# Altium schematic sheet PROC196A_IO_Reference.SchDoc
size A2; Date: Not shown in title block; ApprovedBy: Not shown in title block; CheckedBy: Not shown in title block; Author: Not shown in title block; CompanyName: Not shown in title block; Engineer: Not shown in title block; Organization: Not shown in title block; Address1: Not shown in title block; Address2: Not shown in title block; Address3: Not shown in title block; Address4: Not shown in title block; DocumentNumber: 2; Revision: Use project parameter SCH_Rev; SheetNumber: 2; SheetTotal: 25; PageSetup: Record=PageOptions¦CenterHorizontal=True¦CenterVertical=True¦PrintScale=1.00¦XCorrection=1.00¦YCorrection=1.00¦PrintKind=0¦BorderSize=5000000¦LeftOffset=0¦BottomOffset=0¦Orientation=2¦PaperLength=1000¦PaperWidth=1000¦Scale=100¦PaperSource=15¦PrintQuality=600¦MediaType=1¦DitherType=10¦PaperKind=Letter¦PrintScaleMode=1
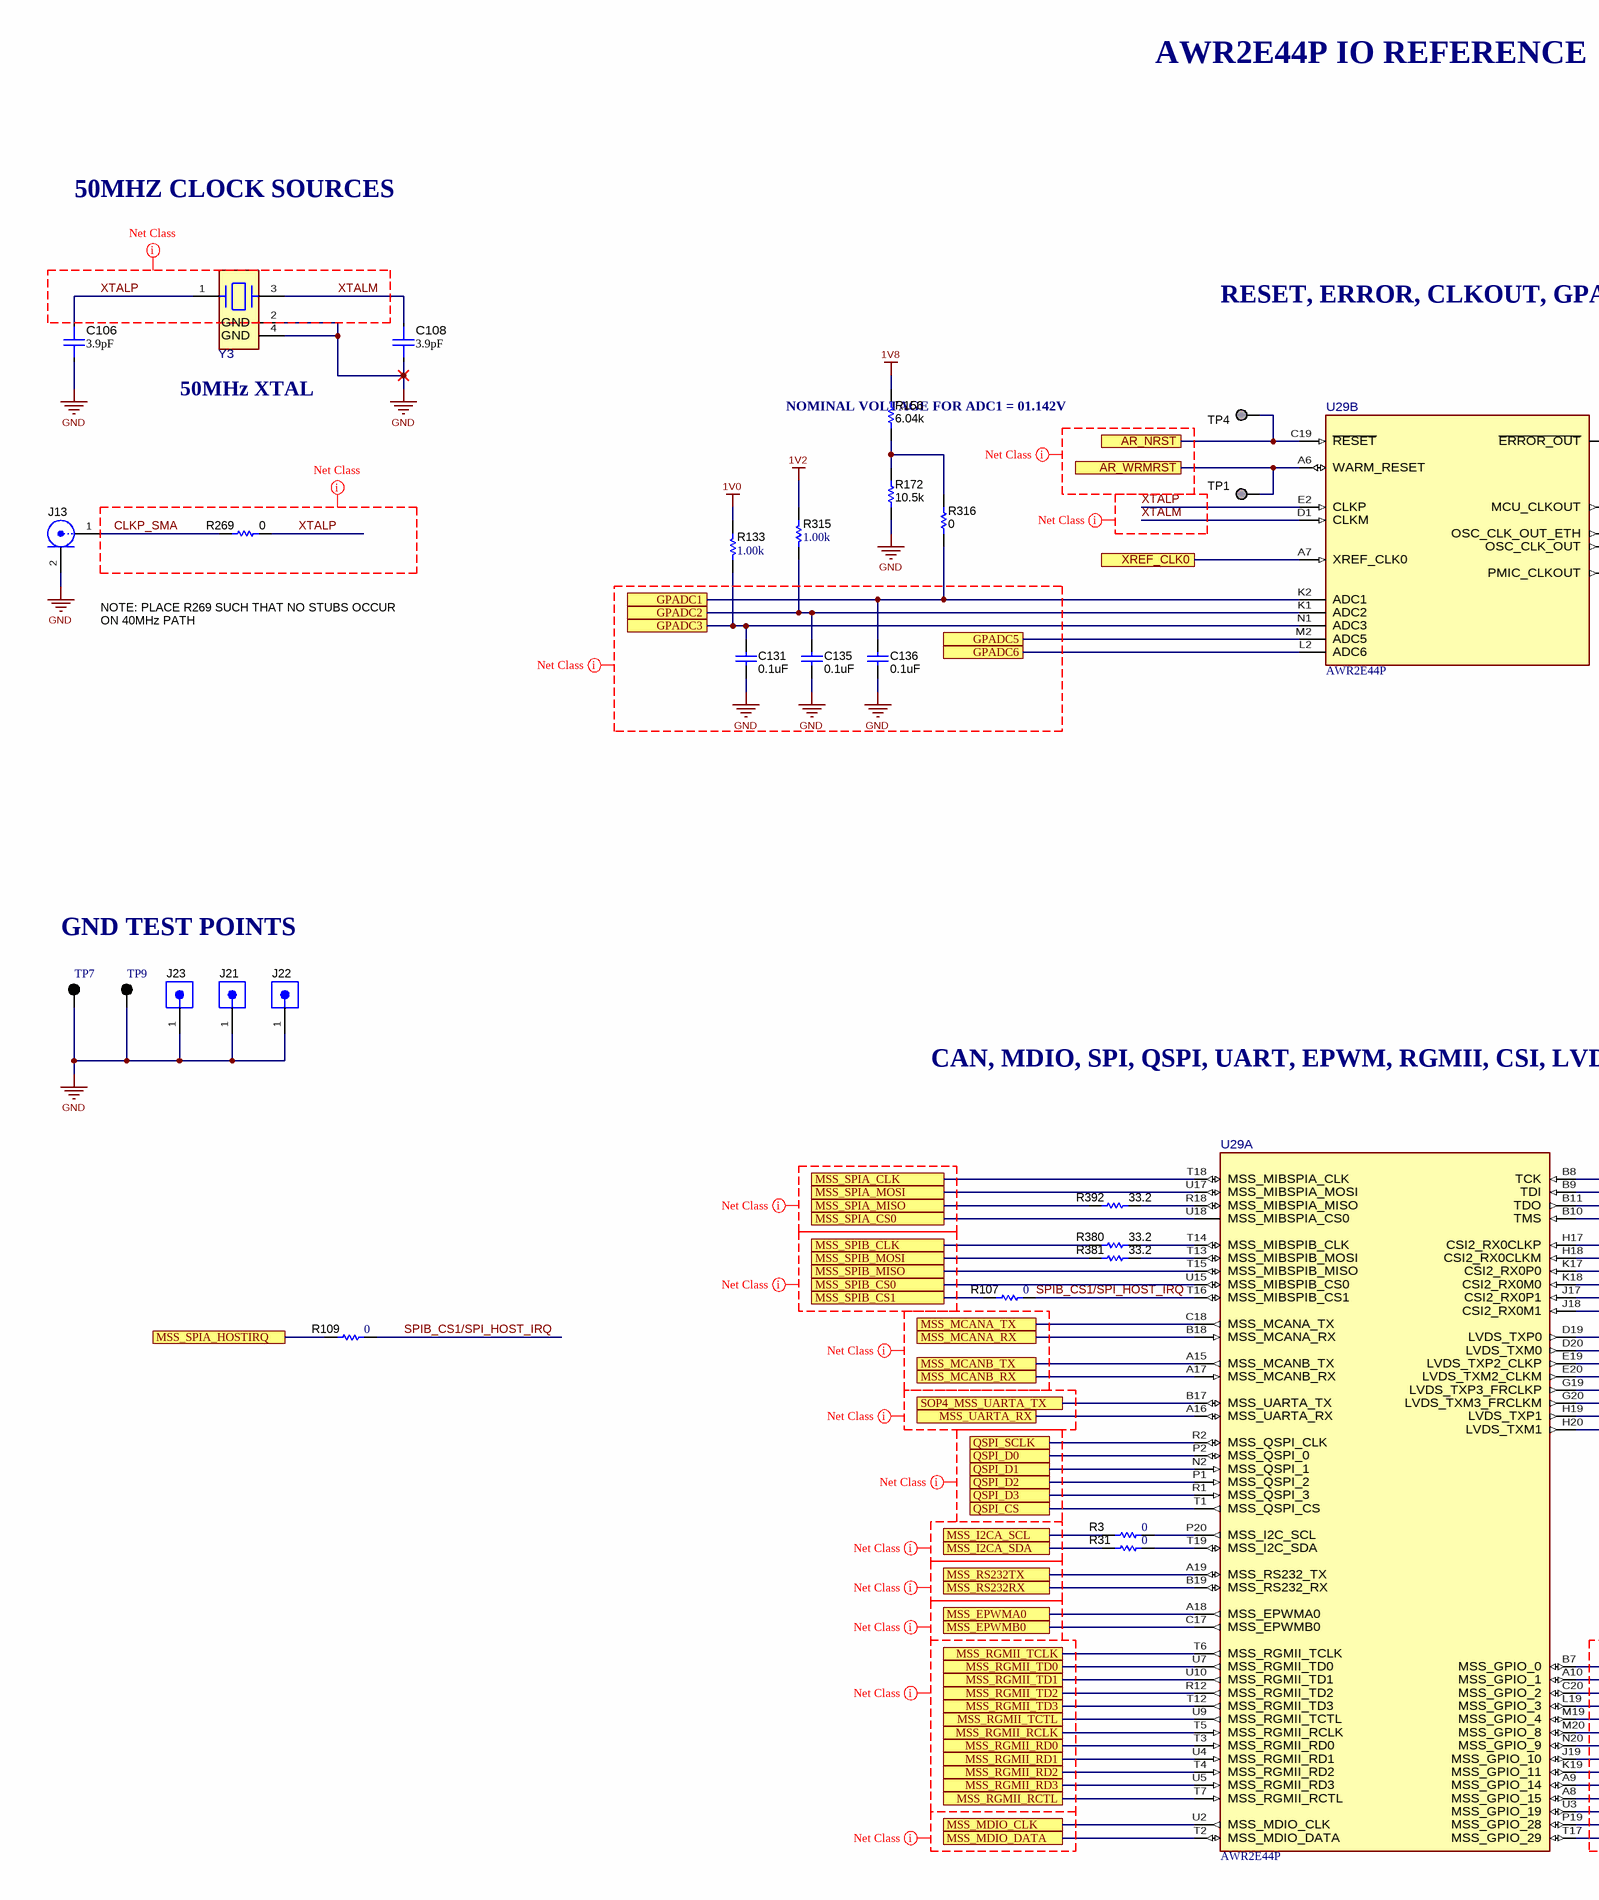
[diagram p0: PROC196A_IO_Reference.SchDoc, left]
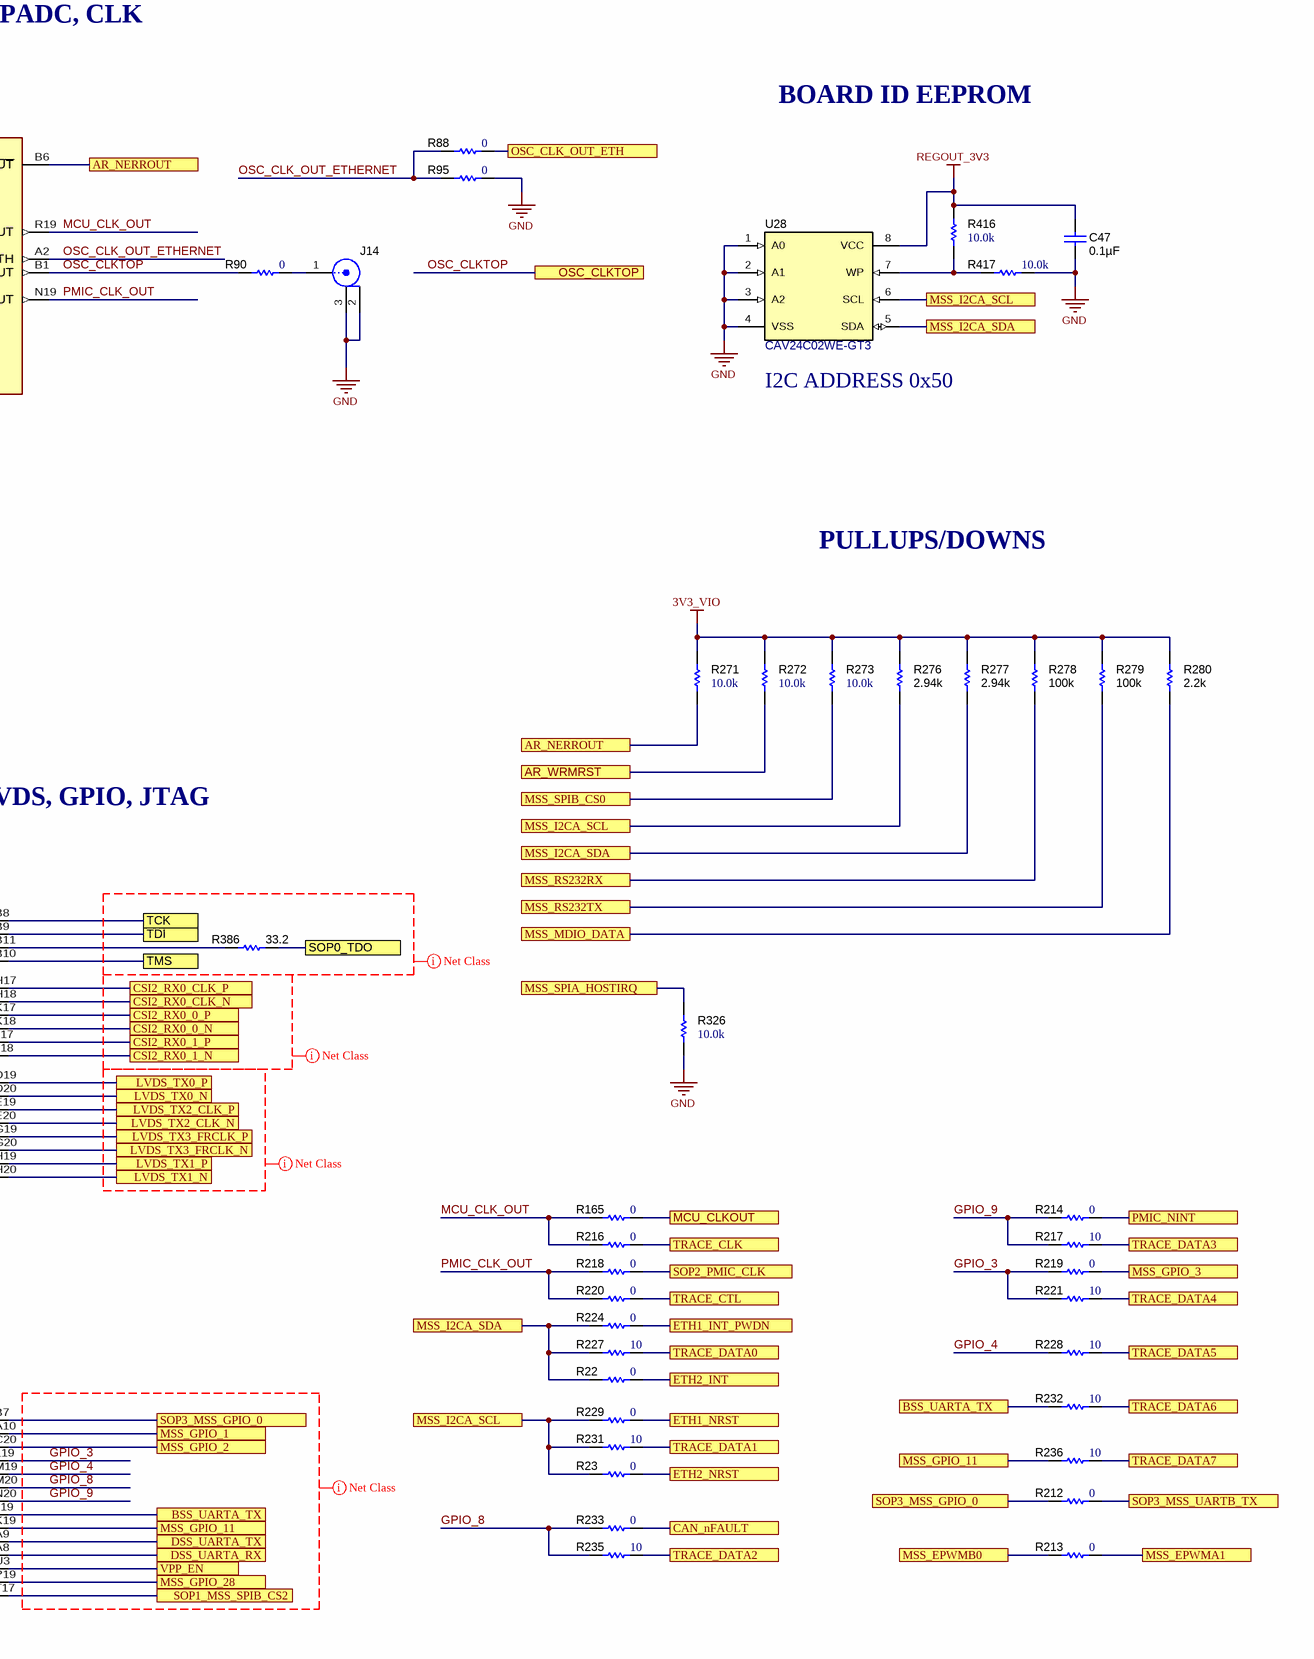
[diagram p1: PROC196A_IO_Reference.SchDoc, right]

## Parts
C47  ValueDisplayed: 0.1µF  [0402L]  (hidden comment: C0402C104K8RACTU)
C106  ValueDisplayed: 3.9pF  [FP-GCM1555C1H3R9BA16D_0402-MFG]  (hidden comment: GCM1555C1H3R9BA16D)
C108  ValueDisplayed: 3.9pF  [FP-GCM1555C1H3R9BA16D_0402-MFG]  (hidden comment: GCM1555C1H3R9BA16D)
C131  ValueDisplayed: 0.1uF  [0402L]  (hidden comment: GCM155R71C104KA55D)
C135  ValueDisplayed: 0.1uF  [0402L]  (hidden comment: GCM155R71C104KA55D)
C136  ValueDisplayed: 0.1uF  [0402L]  (hidden comment: GCM155R71C104KA55D)
J13  142-0711-201  [142-0711-201]  (value not drawn)
J14  128-0711-201  [Johnson_128-0711-201]  (value not drawn)
J21  GBC01SFBN-M30  [Sullins_GBC01SFBN-M30]  (value not drawn)
J22  GBC01SFBN-M30  [Sullins_GBC01SFBN-M30]  (value not drawn)
J23  GBC01SFBN-M30  [Sullins_GBC01SFBN-M30]  (value not drawn)
R3  ValueDisplayed: 0  [0402L]  (hidden comment: ERJ-2GE0R00X)
R22  ValueDisplayed: 0  [0402L]  (hidden comment: ERJ-2GE0R00X)
R23  ValueDisplayed: 0  [0402L]  (hidden comment: ERJ-2GE0R00X)
R31  ValueDisplayed: 0  [0402L]  (hidden comment: ERJ-2GE0R00X)
R88  ValueDisplayed: 0  [0402L]  (hidden comment: ERJ-2GE0R00X)
R90  ValueDisplayed: 0  [0402L]  (hidden comment: ERJ-2GE0R00X)
R95  ValueDisplayed: 0  [0402L]  (hidden comment: ERJ-2GE0R00X)
R107  ValueDisplayed: 0  [0402L]  (hidden comment: ERJ-2GE0R00X)
R109  ValueDisplayed: 0  [0402L]  (hidden comment: ERJ-2GE0R00X)
R133  ValueDisplayed: 1.00k  [0402L]  (hidden comment: CRCW04021K00FKED)
R156  ValueDisplayed: 6.04k  [0402L]  (hidden comment: CRCW04026K04FKED)
R165  ValueDisplayed: 0  [0201L]  (hidden comment: CRCW02010000Z0ED)
R172  ValueDisplayed: 10.5k  [0402L]  (hidden comment: CRCW040210K5FKED)
R212  ValueDisplayed: 0  [0201L]  (hidden comment: CRCW02010000Z0ED)
R213  value 0  [0402L]  (hidden comment: ERJ-2GE0R00X)
R214  value 0  [0402L]  (hidden comment: ERJ-2GE0R00X)
R216  ValueDisplayed: 0  [0201L]  (hidden comment: CRCW02010000Z0ED)
R217  ValueDisplayed: 10  [0201L]  (hidden comment: RC0201JR-0710RL)
R218  ValueDisplayed: 0  [0201L]  (hidden comment: CRCW02010000Z0ED)
R219  ValueDisplayed: 0  [0201L]  (hidden comment: CRCW02010000Z0ED)
R220  ValueDisplayed: 0  [0201L]  (hidden comment: CRCW02010000Z0ED)
R221  ValueDisplayed: 10  [0201L]  (hidden comment: RC0201JR-0710RL)
R224  ValueDisplayed: 0  [0201L]  (hidden comment: CRCW02010000Z0ED)
R227  ValueDisplayed: 10  [0201L]  (hidden comment: RC0201JR-0710RL)
R228  ValueDisplayed: 10  [0201L]  (hidden comment: RC0201JR-0710RL)
R229  ValueDisplayed: 0  [0201L]  (hidden comment: CRCW02010000Z0ED)
R231  ValueDisplayed: 10  [0201L]  (hidden comment: RC0201JR-0710RL)
R232  ValueDisplayed: 10  [0201L]  (hidden comment: RC0201JR-0710RL)
R233  value 0  [0402L]  (hidden comment: ERJ-2GE0R00X)
R235  ValueDisplayed: 10  [0201L]  (hidden comment: RC0201JR-0710RL)
R236  ValueDisplayed: 10  [0201L]  (hidden comment: RC0201JR-0710RL)
R269  ValueDisplayed: 0  [0402L]  (hidden comment: ERJ-2GE0R00X)
R271  ValueDisplayed: 10.0k  [0402L]  (hidden comment: CRCW040210K0FKED)
R272  ValueDisplayed: 10.0k  [0402L]  (hidden comment: CRCW040210K0FKED)
R273  ValueDisplayed: 10.0k  [0402L]  (hidden comment: CRCW040210K0FKED)
R276  ValueDisplayed: 2.94k  [0402L]  (hidden comment: CRCW04022K94FKED)
R277  ValueDisplayed: 2.94k  [0402L]  (hidden comment: CRCW04022K94FKED)
R278  ValueDisplayed: 100k  [0402L]  (hidden comment: CRCW0402100KFKED)
R279  ValueDisplayed: 100k  [0402L]  (hidden comment: CRCW0402100KFKED)
R280  ValueDisplayed: 2.2k  [0402L]  (hidden comment: CRCW04022K20JNED)
R315  ValueDisplayed: 1.00k  [0402L]  (hidden comment: CRCW04021K00FKED)
R316  ValueDisplayed: 0  [0402L]  (hidden comment: ERJ-2GE0R00X)
R326  ValueDisplayed: 10.0k  [0402L]  (hidden comment: CRCW040210K0FKED)
R380  ValueDisplayed: 33.2  [0402L]  (hidden comment: CRCW040233R2FKED)
R381  ValueDisplayed: 33.2  [0402L]  (hidden comment: CRCW040233R2FKED)
R386  ValueDisplayed: 33.2  [0402L]  (hidden comment: CRCW040233R2FKED)
R392  ValueDisplayed: 33.2  [0402L]  (hidden comment: CRCW040233R2FKED)
R416  ValueDisplayed: 10.0k  [0402L]  (hidden comment: CRCW040210K0FKED)
R417  ValueDisplayed: 10.0k  [0402L]  (hidden comment: CRCW040210K0FKED)
TP1  TESTPOINT  [TP_25MIL-SMT]  (value not drawn)  (no BOM)
TP4  TESTPOINT  [TP_25MIL-SMT]  (value not drawn)  (no BOM)
TP7  5001  [Keystone5001]  (value not drawn)
TP9  5001  [Keystone5001]  (value not drawn)
U28  CAV24C02WE-GT3  [SOIC-8]
U29  AWR2E44P  [AMX0278A-MFG]  (parts A,B of 6)
Y3  NX2016SA-50M-STD-CZS-3  [FP-NX2016SA-50M-STD-CZS-3_SMT4_2MM0_1MM6-MFG]  (value not drawn)

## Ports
AR_NERROUT, AR_NRST, AR_WRMRST, BSS_UARTA_TX, CAN_nFAULT, CSI2_RX0_0_N, CSI2_RX0_0_P, CSI2_RX0_1_N, CSI2_RX0_1_P, CSI2_RX0_CLK_N, CSI2_RX0_CLK_P, DSS_UARTA_RX, DSS_UARTA_TX, ETH1_INT_PWDN, ETH1_NRST, ETH2_INT, ETH2_NRST, GPADC1, GPADC2, GPADC3, GPADC5, GPADC6, LVDS_TX0_N, LVDS_TX0_P, LVDS_TX1_N, LVDS_TX1_P, LVDS_TX2_CLK_N, LVDS_TX2_CLK_P, LVDS_TX3_FRCLK_N, LVDS_TX3_FRCLK_P, MCU_CLKOUT, MSS_EPWMA0, MSS_EPWMA1, MSS_EPWMB0, MSS_GPIO_1, MSS_GPIO_2, MSS_GPIO_3, MSS_GPIO_11, MSS_GPIO_28, MSS_I2CA_SCL, MSS_I2CA_SDA, MSS_MCANA_RX, MSS_MCANA_TX, MSS_MCANB_RX, MSS_MCANB_TX, MSS_MDIO_CLK, MSS_MDIO_DATA, MSS_RGMII_RCLK, MSS_RGMII_RCTL, MSS_RGMII_RD0, MSS_RGMII_RD1, MSS_RGMII_RD2, MSS_RGMII_RD3, MSS_RGMII_TCLK, MSS_RGMII_TCTL, MSS_RGMII_TD0, MSS_RGMII_TD1, MSS_RGMII_TD2, MSS_RGMII_TD3, MSS_RS232RX, MSS_RS232TX, MSS_SPIA_CLK, MSS_SPIA_CS0, MSS_SPIA_HOSTIRQ, MSS_SPIA_MISO, MSS_SPIA_MOSI, MSS_SPIB_CLK, MSS_SPIB_CS0, MSS_SPIB_CS1, MSS_SPIB_MISO, MSS_SPIB_MOSI, MSS_UARTA_RX, OSC_CLK_OUT_ETH, OSC_CLKTOP, PMIC_NINT, QSPI_CS, QSPI_D0, QSPI_D1, QSPI_D2, QSPI_D3, QSPI_SCLK, SOP0_TDO, SOP1_MSS_SPIB_CS2, SOP2_PMIC_CLK, SOP3_MSS_GPIO_0, SOP3_MSS_UARTB_TX, SOP4_MSS_UARTA_TX, TCK, TDI, TMS, TRACE_CLK, TRACE_CTL, TRACE_DATA0, TRACE_DATA1, TRACE_DATA2, TRACE_DATA3, TRACE_DATA4, TRACE_DATA5, TRACE_DATA6, TRACE_DATA7, VPP_EN, XREF_CLK0

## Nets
1V0: R133.2
1V2: R315.2
1V8: R156.2
3V3_VIO: R271.2 R272.2 R273.2 R276.2 R277.2 R278.2 R279.2 R280.2
GND: C47.1 C106.2 C108.2 C131.1 C135.1 C136.1 J13.2 J14.2 J14.3 J21.1 J22.1 J23.1 R95.1 R172.1 R326.1 R417.1 TP7.1 TP9.1 U28.1(A0) U28.2(A1) U28.3(A2) U28.4(VSS) Y3.2(GND) Y3.4(GND)
REGOUT_3V3: C47.2 R416.2 U28.8(VCC)
AR_NERROUT: R271.1 U29.B6(~{ERROR_OUT}) ; port AR_NERROUT
AR_NRST: TP4.1 U29.C19(~{RESET}) ; port AR_NRST
AR_WRMRST: R272.1 TP1.1 U29.A6(WARM_RESET) ; port AR_WRMRST
BSS_UARTA_TX: R232.2 U29.J19(MSS_GPIO_10) ; port BSS_UARTA_TX
CAN_nFAULT: R233.2 ; port CAN_nFAULT
CLKP_SMA: J13.1 R269.2
CSI2_RX0_0_N: U29.K18(CSI2_RX0M0) ; port CSI2_RX0_0_N
CSI2_RX0_0_P: U29.K17(CSI2_RX0P0) ; port CSI2_RX0_0_P
CSI2_RX0_1_N: U29.J18(CSI2_RX0M1) ; port CSI2_RX0_1_N
CSI2_RX0_1_P: U29.J17(CSI2_RX0P1) ; port CSI2_RX0_1_P
CSI2_RX0_CLK_N: U29.H18(CSI2_RX0CLKM) ; port CSI2_RX0_CLK_N
CSI2_RX0_CLK_P: U29.H17(CSI2_RX0CLKP) ; port CSI2_RX0_CLK_P
DSS_UARTA_RX: U29.A8(MSS_GPIO_15) ; port DSS_UARTA_RX
DSS_UARTA_TX: U29.A9(MSS_GPIO_14) ; port DSS_UARTA_TX
ETH1_INT_PWDN: R224.2 ; port ETH1_INT_PWDN
ETH1_NRST: R229.2 ; port ETH1_NRST
ETH2_INT: R22.1 ; port ETH2_INT
ETH2_NRST: R23.1 ; port ETH2_NRST
GPADC1: C136.2 R316.1 U29.K2(ADC1) ; port GPADC1
GPADC2: C135.2 R315.1 U29.K1(ADC2) ; port GPADC2
GPADC3: C131.2 R133.1 U29.N1(ADC3) ; port GPADC3
GPADC5: U29.M2(ADC5) ; port GPADC5
GPADC6: U29.L2(ADC6) ; port GPADC6
GPIO_3: R219.1 R221.2 U29.L19(MSS_GPIO_3)
GPIO_4: R228.2 U29.M19(MSS_GPIO_4)
GPIO_8: R233.1 R235.2 U29.M20(MSS_GPIO_8)
GPIO_9: R214.1 R217.2 U29.N20(MSS_GPIO_9)
LVDS_TX0_N: U29.D20(LVDS_TXM0) ; port LVDS_TX0_N
LVDS_TX0_P: U29.D19(LVDS_TXP0) ; port LVDS_TX0_P
LVDS_TX1_N: U29.H20(LVDS_TXM1) ; port LVDS_TX1_N
LVDS_TX1_P: U29.H19(LVDS_TXP1) ; port LVDS_TX1_P
LVDS_TX2_CLK_N: U29.E20(LVDS_TXM2_CLKM) ; port LVDS_TX2_CLK_N
LVDS_TX2_CLK_P: U29.E19(LVDS_TXP2_CLKP) ; port LVDS_TX2_CLK_P
LVDS_TX3_FRCLK_N: U29.G20(LVDS_TXM3_FRCLKM) ; port LVDS_TX3_FRCLK_N
LVDS_TX3_FRCLK_P: U29.G19(LVDS_TXP3_FRCLKP) ; port LVDS_TX3_FRCLK_P
MCU_CLK_OUT: R165.1 R216.1 U29.R19(MCU_CLKOUT)
MCU_CLKOUT: R165.2 ; port MCU_CLKOUT
MSS_EPWMA0: U29.A18(MSS_EPWMA0) ; port MSS_EPWMA0
MSS_EPWMA1: R213.2 ; port MSS_EPWMA1
MSS_EPWMB0: R213.1 U29.C17(MSS_EPWMB0) ; port MSS_EPWMB0
MSS_GPIO_1: U29.A10(MSS_GPIO_1) ; port MSS_GPIO_1
MSS_GPIO_2: U29.C20(MSS_GPIO_2) ; port MSS_GPIO_2
MSS_GPIO_3: R219.2 ; port MSS_GPIO_3
MSS_GPIO_11: R236.2 U29.K19(MSS_GPIO_11) ; port MSS_GPIO_11
MSS_GPIO_28: U29.P19(MSS_GPIO_28) ; port MSS_GPIO_28
MSS_I2CA_SCL: R3.1 R23.2 R229.1 R231.2 R276.1 U28.6(SCL) ; port MSS_I2CA_SCL
MSS_I2CA_SDA: R22.2 R31.1 R224.1 R227.2 R277.1 U28.5(SDA) ; port MSS_I2CA_SDA
MSS_MCANA_RX: U29.B18(MSS_MCANA_RX) ; port MSS_MCANA_RX
MSS_MCANA_TX: U29.C18(MSS_MCANA_TX) ; port MSS_MCANA_TX
MSS_MCANB_RX: U29.A17(MSS_MCANB_RX) ; port MSS_MCANB_RX
MSS_MCANB_TX: U29.A15(MSS_MCANB_TX) ; port MSS_MCANB_TX
MSS_MDIO_CLK: U29.U2(MSS_MDIO_CLK) ; port MSS_MDIO_CLK
MSS_MDIO_DATA: R280.1 U29.T2(MSS_MDIO_DATA) ; port MSS_MDIO_DATA
MSS_RGMII_RCLK: U29.T5(MSS_RGMII_RCLK) ; port MSS_RGMII_RCLK
MSS_RGMII_RCTL: U29.T7(MSS_RGMII_RCTL) ; port MSS_RGMII_RCTL
MSS_RGMII_RD0: U29.T3(MSS_RGMII_RD0) ; port MSS_RGMII_RD0
MSS_RGMII_RD1: U29.U4(MSS_RGMII_RD1) ; port MSS_RGMII_RD1
MSS_RGMII_RD2: U29.T4(MSS_RGMII_RD2) ; port MSS_RGMII_RD2
MSS_RGMII_RD3: U29.U5(MSS_RGMII_RD3) ; port MSS_RGMII_RD3
MSS_RGMII_TCLK: U29.T6(MSS_RGMII_TCLK) ; port MSS_RGMII_TCLK
MSS_RGMII_TCTL: U29.U9(MSS_RGMII_TCTL) ; port MSS_RGMII_TCTL
MSS_RGMII_TD0: U29.U7(MSS_RGMII_TD0) ; port MSS_RGMII_TD0
MSS_RGMII_TD1: U29.U10(MSS_RGMII_TD1) ; port MSS_RGMII_TD1
MSS_RGMII_TD2: U29.R12(MSS_RGMII_TD2) ; port MSS_RGMII_TD2
MSS_RGMII_TD3: U29.T12(MSS_RGMII_TD3) ; port MSS_RGMII_TD3
MSS_RS232RX: R278.1 U29.B19(MSS_RS232_RX) ; port MSS_RS232RX
MSS_RS232TX: R279.1 U29.A19(MSS_RS232_TX) ; port MSS_RS232TX
MSS_SPIA_CLK: U29.T18(MSS_MIBSPIA_CLK) ; port MSS_SPIA_CLK
MSS_SPIA_CS0: U29.U18(MSS_MIBSPIA_CS0) ; port MSS_SPIA_CS0
MSS_SPIA_HOSTIRQ: R109.1 R326.2 ; port MSS_SPIA_HOSTIRQ
MSS_SPIA_MISO: R392.1 ; port MSS_SPIA_MISO
MSS_SPIA_MOSI: U29.U17(MSS_MIBSPIA_MOSI) ; port MSS_SPIA_MOSI
MSS_SPIB_CLK: R380.1 ; port MSS_SPIB_CLK
MSS_SPIB_CS0: R273.1 U29.U15(MSS_MIBSPIB_CS0) ; port MSS_SPIB_CS0
MSS_SPIB_CS1: R107.1 ; port MSS_SPIB_CS1
MSS_SPIB_MISO: U29.T15(MSS_MIBSPIB_MISO) ; port MSS_SPIB_MISO
MSS_SPIB_MOSI: R381.1 ; port MSS_SPIB_MOSI
MSS_UARTA_RX: U29.A16(MSS_UARTA_RX) ; port MSS_UARTA_RX
OSC_CLK_OUT_ETH: R88.1 ; port OSC_CLK_OUT_ETH
OSC_CLK_OUT_ETHERNET: R88.2 R95.2 U29.A2(OSC_CLK_OUT_ETH)
OSC_CLKTOP: R90.1 U29.B1(OSC_CLK_OUT) ; port OSC_CLKTOP
PMIC_CLK_OUT: R218.1 R220.1 U29.N19(PMIC_CLKOUT)
PMIC_NINT: R214.2 ; port PMIC_NINT
QSPI_CS: U29.T1(MSS_QSPI_CS) ; port QSPI_CS
QSPI_D0: U29.P2(MSS_QSPI_0) ; port QSPI_D0
QSPI_D1: U29.N2(MSS_QSPI_1) ; port QSPI_D1
QSPI_D2: U29.P1(MSS_QSPI_2) ; port QSPI_D2
QSPI_D3: U29.R1(MSS_QSPI_3) ; port QSPI_D3
QSPI_SCLK: U29.R2(MSS_QSPI_CLK) ; port QSPI_SCLK
SOP0_TDO: R386.1 ; port SOP0_TDO
SOP1_MSS_SPIB_CS2: U29.T17(MSS_GPIO_29) ; port SOP1_MSS_SPIB_CS2
SOP2_PMIC_CLK: R218.2 ; port SOP2_PMIC_CLK
SOP3_MSS_GPIO_0: R212.1 U29.B7(MSS_GPIO_0) ; port SOP3_MSS_GPIO_0
SOP3_MSS_UARTB_TX: R212.2 ; port SOP3_MSS_UARTB_TX
SOP4_MSS_UARTA_TX: U29.B17(MSS_UARTA_TX) ; port SOP4_MSS_UARTA_TX
SPIB_CS1/SPI_HOST_IRQ: R107.2 R109.2 U29.T16(MSS_MIBSPIB_CS1)
TCK: U29.B8(TCK) ; port TCK
TDI: U29.B9(TDI) ; port TDI
TMS: U29.B10(TMS) ; port TMS
TRACE_CLK: R216.2 ; port TRACE_CLK
TRACE_CTL: R220.2 ; port TRACE_CTL
TRACE_DATA0: R227.1 ; port TRACE_DATA0
TRACE_DATA1: R231.1 ; port TRACE_DATA1
TRACE_DATA2: R235.1 ; port TRACE_DATA2
TRACE_DATA3: R217.1 ; port TRACE_DATA3
TRACE_DATA4: R221.1 ; port TRACE_DATA4
TRACE_DATA5: R228.1 ; port TRACE_DATA5
TRACE_DATA6: R232.1 ; port TRACE_DATA6
TRACE_DATA7: R236.1 ; port TRACE_DATA7
VPP_EN: U29.U3(MSS_GPIO_19) ; port VPP_EN
XREF_CLK0: U29.A7(XREF_CLK0) ; port XREF_CLK0
XTALM: C108.1 U29.D1(CLKM) Y3.3(2_XTAL)
XTALP: C106.1 R269.1 U29.E2(CLKP) Y3.1(1_XTAL)
NetJ14_1: J14.1 R90.2
NetR3_2: R3.2 U29.P20(MSS_I2C_SCL)
NetR31_2: R31.2 U29.T19(MSS_I2C_SDA)
NetR156_1: R156.1 R172.2 R316.2
NetR380_2: R380.2 U29.T14(MSS_MIBSPIB_CLK)
NetR381_2: R381.2 U29.T13(MSS_MIBSPIB_MOSI)
NetR386_2: R386.2 U29.B11(TDO)
NetR392_2: R392.2 U29.R18(MSS_MIBSPIA_MISO)
NetR416_1: R416.1 R417.2 U28.7(WP)

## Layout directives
net class CAN: (no net found under the mark)
net class 40MHz_CLK: CLKP_SMA, XTALM, XTALP
net class RGMII_TX_RX: (no net found under the mark)
net class GPADC: GND
net class I2C: (no net found under the mark)
net class MSS_SPIA: (no net found under the mark)
net class MSS_SPIB: (no net found under the mark)
net class QSPI: (no net found under the mark)
net class CSI: (no net found under the mark)
net class EPWM: (no net found under the mark)
net class JTAG: (no net found under the mark)
net class RESET: (no net found under the mark)
net class LVDS: (no net found under the mark)
net class UART: (no net found under the mark)
net class GPIO: GPIO_3, GPIO_4, GPIO_8, GPIO_9
net class MDIO: (no net found under the mark)

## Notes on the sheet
- AWR2E44P IO REFERENCE
- 50MHZ CLOCK SOURCES
- RESET, ERROR, CLKOUT, GPADC, CLK
- (near Y3) 50MHz XTAL
- NOMINAL VOLTAGE FOR ADC1 = 01.142V
- BOARD ID EEPROM
- NOTE: PLACE R269 SUCH THAT NO STUBS OCCUR ON 40MHz PATH
- (near U28) I2C ADDRESS 0x50
- PULLUPS/DOWNS
- GND TEST POINTS
- CAN, MDIO, SPI, QSPI, UART, EPWM, RGMII, CSI, LVDS, GPIO, JTAG

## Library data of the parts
C47 = CMP-0078241-1: CAP, CERM, 0.1 µF, 10 V,+/- 10%, X7R, 0402; Manufacturer: Kemet; TaMin_C: -55°C; Polarized: N; SizeAreaWB_mm2: 3; U/M: EA; Value: 0.1uF; TaMax_C: 125°C; SizeZ_mm: 0.6; SizeX_mm: 1; SizeY_mm: 0.5; Cap_Case: 0402; Value2: 10V; Cap_F: 100nF; AEC Category: Q200
C106 C108 = CMP-0048219-1: Ceramic Capacitor for Automotive 3.9pF ±0.1pF 50VDC C0G 0402 Paper T/R; Manufacturer: Murata; AEC Grade: Grade 1; AEC Qualified: Yes; SizeZ_mm: 0.55mm; TempCo: 30ppm/°C; VDC_V: 50V
C131 C135 C136 = CMP-0006351-2: CAP, CERM, 0.1 uF, 16 V, +/- 10%, X7R, 0402; Manufacturer: MuRata; TaMin_C: -55°C; Polarized: N; SizeAreaWB_mm2: 3; Value1: Unknown; U/M: EA; Value: 0.1uF; TaMax_C: 125°C; SizeZ_mm: 0.6; SizeX_mm: 1; SizeY_mm: 0.5; Cap_Case: 0402; Value2: 16V; CompType: Capacitor; Cap_F: 100nF; AEC Category: Q200
J13 = CMP-0055823-2: Connector, SMA Jack, Vertical, Gold, SMD; Manufacturer: Cinch Connectivity; Green_REACh: Incomplete; Green_Lifecycle: Not Set; Gender: Female
J14 = CMP-0055788-1: UMC Straight Jack Receptacle, 50 Ohm, Gold, SMT; Manufacturer: Cinch Connectivity; CNHeader: FALSE; Gender: Female
J21-J23 = CMP-0084373-1: Header, 1x1, Gold, SMT; Manufacturer: Sullins Connector Solutions; Cert_UL: Y; Current_A: 3A; Gender: Male; Row_Count: 1; Shrouded: N
R3 R22 R23 R31 R88 R90 R95 R107 R109 R269 R316 = CMP-0026992-3: RES, 0, 5%, 0.1 W, AEC-Q200 Grade 0, 0402; Manufacturer: Panasonic; Power_W: 100mW; TempCo: 600 ppm/C; Value_Code: 0000; Value: 0; EIA_Code: E24; SizeX_mm: 1; SizeY_mm: 0.5; SizeZ_mm: 0.6; Value2: 0.1W; AEC Qualified: Y; VDC_V: 50V; AEC Category: Q200; SizeAreaWB_mm2: 3
R133 R315 = CMP-0026071-3: RES, 1.00 k, 1%, 0.063 W, AEC-Q200 Grade 0, 0402; Manufacturer: Vishay-Dale; Power_W: 63mW; TempCo: 100 ppm/C; Value_Code: 1k00; Value: 1.00k; EIA_Code: E96; Res_ohm: 1k; SizeX_mm: 1; SizeY_mm: 0.5; SizeZ_mm: 0.6; Value2: 0.063W; AEC Qualified: Y; VDC_V: 50V; AEC Category: Q200; AEC Grade: 0
R156 = CMP-0026512-2: RES, 6.04 k, 1%, 0.063 W, AEC-Q200 Grade 0, 0402; Manufacturer: Vishay-Dale; Power_W: 63mW; TempCo: 100 ppm/C; Value_Code: 6k04; Value: 6.04k; EIA_Code: E96; SizeX_mm: 1; SizeY_mm: 0.5; SizeZ_mm: 0.6; Value2: 0.063W; AEC Qualified: Y; VDC_V: 50V; AEC Category: Q200; AEC Grade: 0
R165 R212 R216 R218-R220 R224 R229 = CMP-0027008-4: RES, 0, 5%, 0.05 W, 0201; Manufacturer: Vishay-Dale; Power_W: 50mW; TempCo: ppm/C; Value_Code: 0000; Value: 0; EIA_Code: E24; SizeX_mm: 0.6; SizeY_mm: 0.3; SizeZ_mm: 0.26; Value2: 0.05W; SizeArea_mm2: 0.18; AEC Qualified: N; AEC Category: Q200
R172 = CMP-0025960-3: RES, 10.5 k, 1%, 0.063 W, AEC-Q200 Grade 0, 0402; Manufacturer: Vishay-Dale; Power_W: 63mW; TempCo: 100 ppm/C; Value_Code: 10k5; Value: 10.5k; EIA_Code: E96; SizeX_mm: 1; SizeY_mm: 0.5; SizeZ_mm: 0.6; Value2: 0.063W; AEC Qualified: Y; VDC_V: 50V; AEC Category: Q200; AEC Grade: 0
R213 R214 R233 = CMP-0026992-3: RES, 0, 5%, 0.1 W, AEC-Q200 Grade 0, 0402; Manufacturer: Panasonic; Power_W: 100mW; TempCo: 600 ppm/C; Value_Code: 0000; EIA_Code: E24; SizeX_mm: 1; SizeY_mm: 0.5; SizeZ_mm: 0.6; Value2: 0.1W; AEC Qualified: Y; VDC_V: 50V; AEC Category: Q200; SizeAreaWB_mm2: 3
R217 R221 R227 R228 R231 R232 R235 R236 = CMP-0027021-3: RES, 10, 5%, 0.05 W, 0201; Manufacturer: Yageo America; Power_W: 50mW; TempCo: 350 ppm/C; Value_Code: 10R0; U/M: EA; Value: 10; EIA_Code: E24; SizeX_mm: 0.6; SizeY_mm: 0.3; SizeZ_mm: 0.26; Value2: 0.05W; SizeArea_mm2: 0.18; AEC Qualified: N; VDC_V: 25V; AEC Category: Q200
R271-R273 R326 R416 R417 = CMP-0025958-3: RES, 10.0 k, 1%, 0.063 W, AEC-Q200 Grade 0, 0402; Manufacturer: Vishay-Dale; Power_W: 63mW; TempCo: 100 ppm/C; Value_Code: 10k0; Value: 10.0k; EIA_Code: E96; Res_ohm: 10k; SizeX_mm: 1; SizeY_mm: 0.5; SizeZ_mm: 0.6; Value2: 0.063W; CompType: Resistor; AEC Qualified: Y; VDC_V: 50V; AEC Category: Q200; AEC Grade: 0; INSTALLATION: DNP
R276 R277 = CMP-0026244-2: RES, 2.94 k, 1%, 0.063 W, AEC-Q200 Grade 0, 0402; Manufacturer: Vishay-Dale; Power_W: 63mW; TempCo: 100 ppm/C; Value_Code: 2k94; Value: 2.94k; EIA_Code: E96; SizeX_mm: 1; SizeY_mm: 0.5; SizeZ_mm: 0.6; Value2: 0.063W; AEC Qualified: Y; VDC_V: 50V; AEC Category: Q200; AEC Grade: 0
R278 R279 = CMP-0025950-3: RES, 100 k, 1%, 0.063 W, AEC-Q200 Grade 0, 0402; Manufacturer: Vishay-Dale; Power_W: 63mW; TempCo: 100 ppm/C; Value: 100k; EIA_Code: E96; SizeX_mm: 1; SizeY_mm: 0.5; SizeZ_mm: 0.6; Value2: 0.063W; AEC Qualified: Y; VDC_V: 50V; AEC Category: Q200; AEC Grade: 0
R280 = CMP-0026890-5: RES, 2.2 k, 5%, 0.063 W, AEC-Q200 Grade 0, 0402; Manufacturer: Vishay-Dale; Power_W: 63mW; TempCo: 200 ppm/C; Value_Code: 2k20; Value: 2.2k; EIA_Code: E24; SizeX_mm: 1; SizeY_mm: 0.5; SizeZ_mm: 0.6; Value2: 0.063W; AEC Qualified: Y; VDC_V: 50V; AEC Category: Q200; AEC Grade: 0
R380 R381 R386 R392 = CMP-0026299-2: RES, 33.2, 1%, 0.063 W, AEC-Q200 Grade 0, 0402; Manufacturer: Vishay-Dale; Power_W: 63mW; TempCo: 100 ppm/C; Value_Code: 33R2; Value: 33.2; EIA_Code: E96; SizeX_mm: 1; SizeY_mm: 0.5; SizeZ_mm: 0.6; Value2: 0.063W; AEC Qualified: Y; VDC_V: 50V; AEC Category: Q200; AEC Grade: 0
TP1 TP4 = CMP-0078143-3: TEST POINT.  No entry in BOM.
TP7 TP9 = CMP-0055138-1: Test Point, Miniature, Black, TH; Manufacturer: Keystone; CNHeader: FALSE; Green_Lifecycle: Active; Green_REACh: Passed; ContactFinish: Silver; CT: TRUE
U28 = CMP-0005318-2: 2-Kb, 4-Kb, 8-Kb and 16-Kb I2C CMOS Serial EEPROM, SOIC-8; Manufacturer: ON Semiconductor; SizeAreaWB_mm2: 55.131; SizeZ_mm: 1.75; SizeX_mm: 5.99; SizeY_mm: 4.9; SizeArea_mm2: 29.351
U29 = CMP-0122080-1: Manufacturer: Texas Instruments; SizeZ_mm: 1.234mm; Standoff Height: 0.216mm
Y3 = CMP-0001431-1: 50 MHz ±15ppm Crystal 8pF 50 Ohms 4-SMD, No Lead; Manufacturer: NDK; Frequency Stability: 50ppm; Frequency_Fixed: 50MHz; SizeZ_mm: 0.5mm; AEC Qualified: Yes; AEC Grade: Grade 1; Esr: 50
